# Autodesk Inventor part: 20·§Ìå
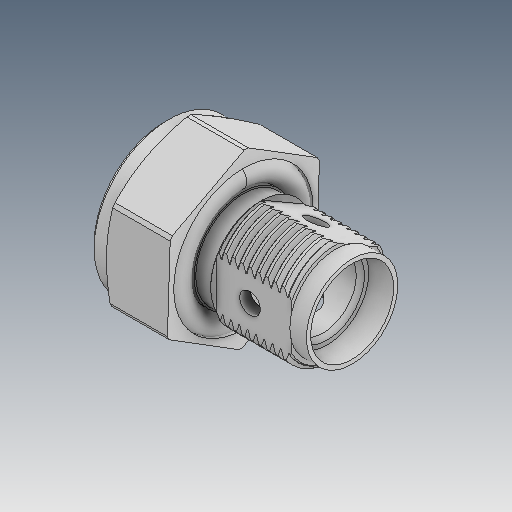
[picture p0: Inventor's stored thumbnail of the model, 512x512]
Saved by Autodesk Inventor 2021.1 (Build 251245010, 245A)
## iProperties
Created: 2019-12
Part Number: 20·§Ìå
Material: Ogólny
Document SubType Name: Modeling
Designer: user
Density: 1 g/cm^3
Appearance: Domyślna
Author: user
Revision Number: ÈÎºÎ
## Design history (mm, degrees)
feature "ÊäÈë1"
feature "ÊäÈë2"
node "Bryła1"
node "Bryła2"
